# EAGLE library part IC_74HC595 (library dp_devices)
8-bit serial-in parallel out shift register, output latch 3-state
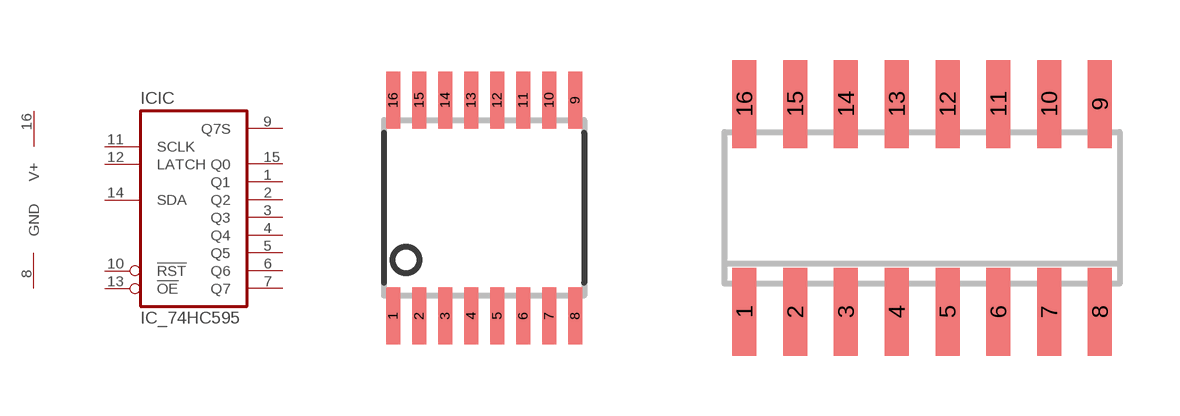
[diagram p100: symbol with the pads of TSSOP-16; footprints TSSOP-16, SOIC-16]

Designator prefix IC; gates IC=74595 SUP=SUPPLY

## IC_74HC595-TSSOP-16  [TSSOP-16]
1  IC:Q1  out
2  IC:Q2  out
3  IC:Q3  out
4  IC:Q4  out
5  IC:Q5  out
6  IC:Q6  out
7  IC:Q7  out
8  SUP:GND  sup
9  IC:Q7S  out
10  IC:!RST  in
11  IC:SCLK  in
12  IC:LATCH  in
13  IC:!OE  in
14  IC:SDA  in
15  IC:Q0  out
16  SUP:V+  sup

## IC_74HC595-SOIC-16  [SOIC-16]
Pads as for TSSOP-16

## IC_74HC595-DIP-16  [DIL16]
Pads as for TSSOP-16

## Footprint TSSOP-16 (pad centres in mm)
smd 0.35 x 1.43: 1 -2.275,-2.7; 2 -1.625,-2.7; 3 -0.975,-2.7; 4 -0.325,-2.7; 5 0.325,-2.7; 6 0.975,-2.7; 7 1.625,-2.7; 8 2.275,-2.7; 9 2.275,2.7; 10 1.625,2.7; 11 0.975,2.7; 12 0.325,2.7; 13 -0.325,2.7; 14 -0.975,2.7; 15 -1.625,2.7; 16 -2.275,2.7

## Footprint SOIC-16 (pad centres in mm)
smd 0.6 x 2.2: 1 -4.445,-2.6; 2 -3.175,-2.6; 3 -1.905,-2.6; 4 -0.635,-2.6; 5 0.635,-2.6; 6 1.905,-2.6; 7 3.175,-2.6; 8 4.445,-2.6; 9 4.445,2.6; 10 3.175,2.6; 11 1.905,2.6; 12 0.635,2.6; 13 -0.635,2.6; 14 -1.905,2.6; 15 -3.175,2.6; 16 -4.445,2.6

## Footprint DIL16 (pad centres in mm)
DIL-16
drill 0.813 long: 1 -8.89,-3.81; 2 -6.35,-3.81; 3 -3.81,-3.81; 4 -1.27,-3.81; 5 1.27,-3.81; 6 3.81,-3.81; 7 6.35,-3.81; 8 8.89,-3.81; 9 8.89,3.81; 10 6.35,3.81; 11 3.81,3.81; 12 1.27,3.81; 13 -1.27,3.81; 14 -3.81,3.81; 15 -6.35,3.81; 16 -8.89,3.81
